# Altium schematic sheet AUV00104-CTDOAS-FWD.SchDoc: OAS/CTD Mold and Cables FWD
size Tabloid; Organization: Monterey Bay Aquarium Research Institute; Address1: 7700 Sandholdt Rd; Address2: Moss Landing, CA 95039-9644; DocumentNumber: AUV00104; Revision: 1; SheetNumber: 1; SheetTotal: 1; CompanyName: MBARI; Engineer: Mark Sibenac
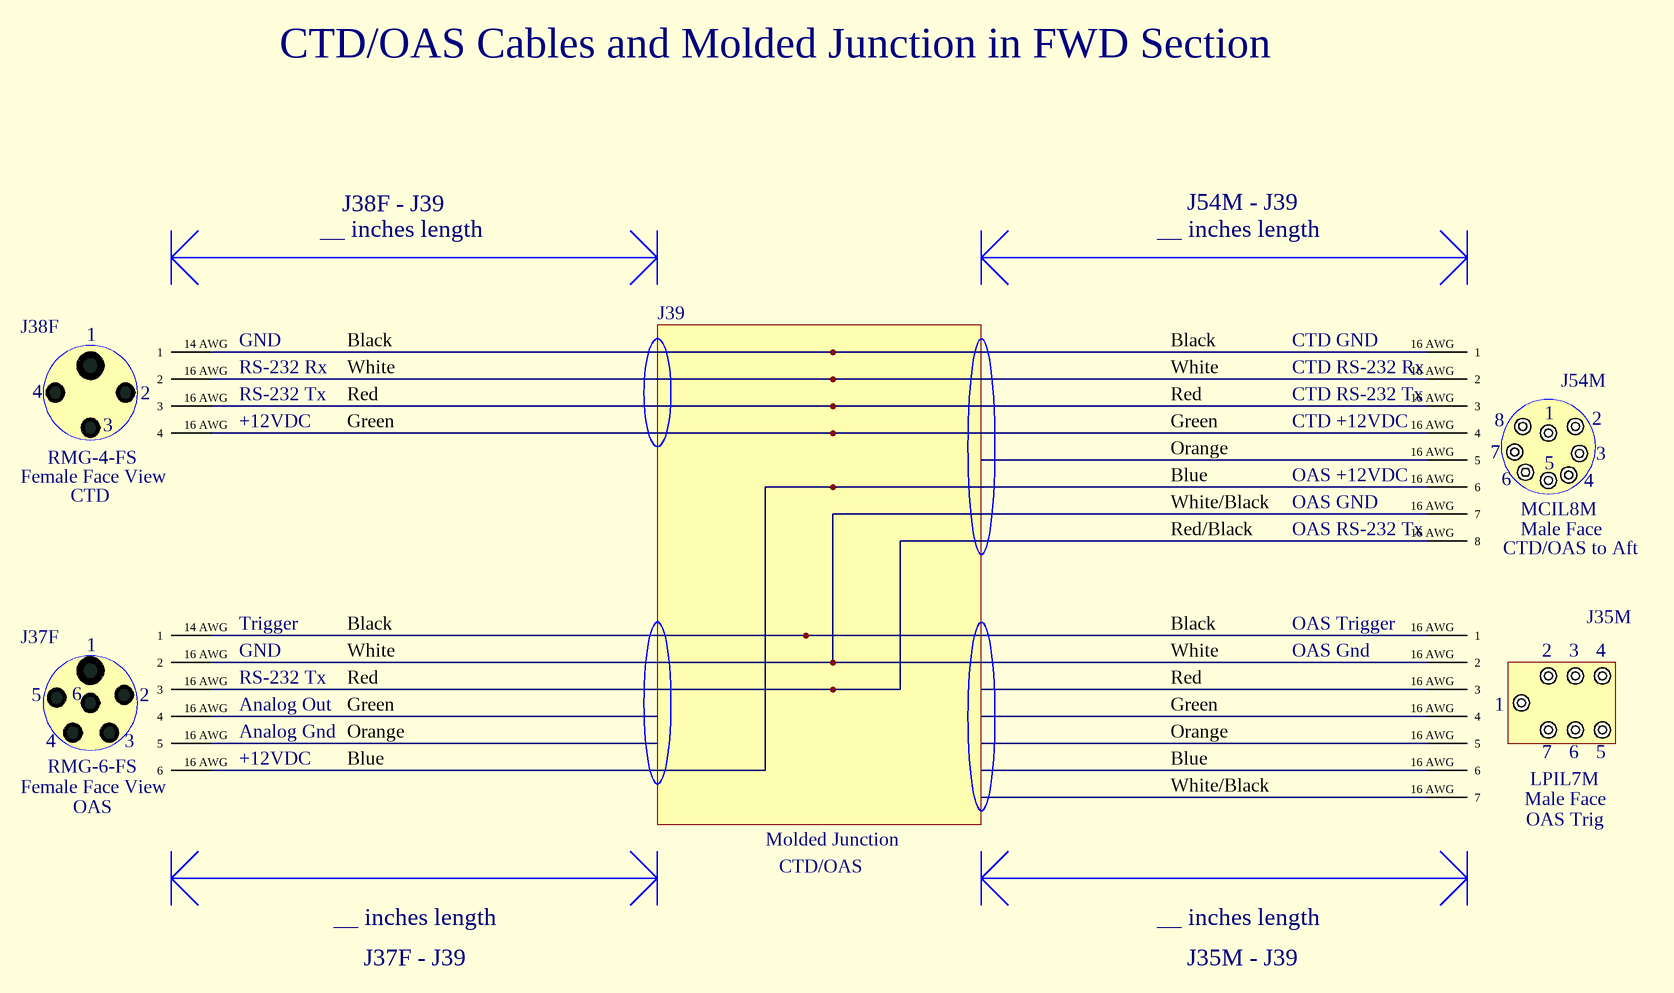
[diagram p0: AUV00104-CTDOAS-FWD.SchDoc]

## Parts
J35M  LPIL7M  View: Male Face  DescSheet: OAS Trig
J37F  RMG-6-FS  DescSheet: OAS
J38F  RMG-4-FS  DescSheet: CTD
J54M  MCIL8M  DescSheet: CTD/OAS to Aft  View: Male Face

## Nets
NetJ35M_16 AWG: J35M.16_AWG(1) J37F.14_AWG(1)
NetJ35M_16 AWG: J35M.16_AWG(2) J37F.16_AWG(2) J54M.16_AWG(7)  [a separate net that carries the same name]
NetJ37F_16 AWG: J37F.16_AWG(3) J54M.16_AWG(8)
NetJ37F_16 AWG: J37F.16_AWG(6) J54M.16_AWG(6)  [a separate net that carries the same name]
NetJ38F_14 AWG: J38F.14_AWG(1) J54M.16_AWG(1)
NetJ38F_16 AWG: J38F.16_AWG(2) J54M.16_AWG(2)
NetJ38F_16 AWG: J38F.16_AWG(3) J54M.16_AWG(3)  [a separate net that carries the same name]
NetJ38F_16 AWG: J38F.16_AWG(4) J54M.16_AWG(4)  [a separate net that carries the same name]

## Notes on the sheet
- CTD/OAS Cables and Molded Junction in FWD Section
- __ inches length
- J38F - J39
- J54M - J39
- J39
- GND
- RS-232 Rx
- RS-232 Tx
- Black
- White
- Red
- (near J54M) CTD RS-232 Rx
- (near J54M) CTD RS-232 Tx
- CTD GND
- +12VDC
- Green
- Orange
- CTD +12VDC
- Blue
- White/Black
- Red/Black
- OAS GND
- OAS +12VDC
- (near J54M) OAS RS-232 Tx
- Trigger
- OAS Trigger
- OAS Gnd
- Analog Out
- Analog Gnd
- Molded Junction
- CTD/OAS
- J37F - J39
- J35M - J39

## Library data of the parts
J35M = SUBCONN-LPXX7M: Subconn LPIL7M Connector
J37F = IMPULSE-RMG-6-FS: Impulse RMG-6-FS Connector; View: Female Face
J38F = IMPULSE-RMG-4-FS: Impulse RMG-4-FS Connector; View: Female Face
J54M = SUBCONN-MCxx8M: Subconn MCIL8M Connector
